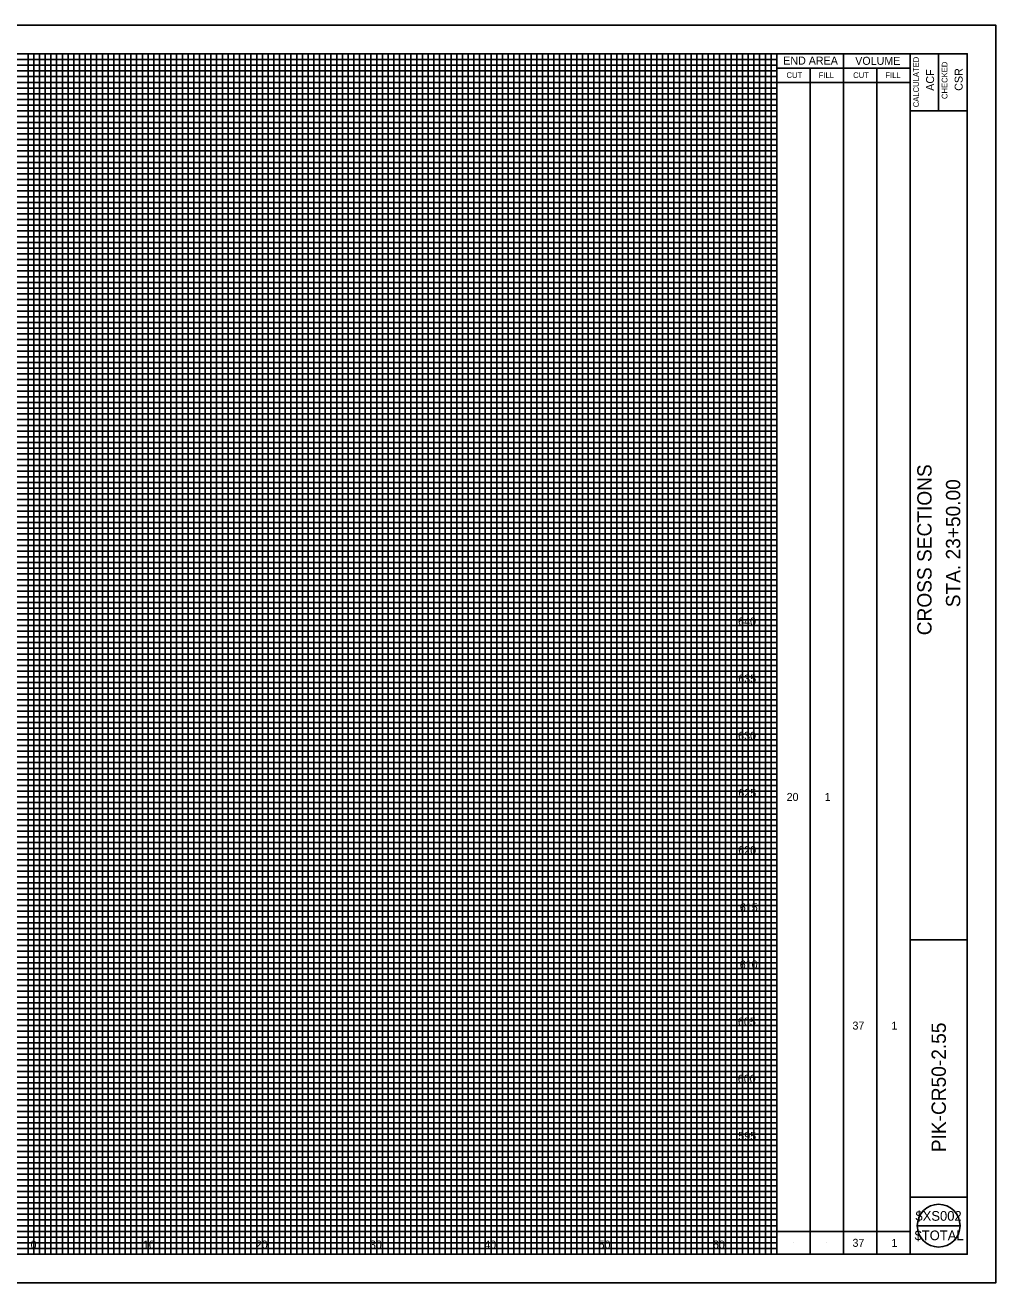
# Model space of a CAD drawing. Extents: x 1858928 to 1859278, y 421672 to 422012.
# Drawn here: x 1859012.6 to 1859097.5, y 421786.6 to 421896.6 of the extents above; entities that cross this region are included whole.
import ezdxf

# ---------------------------------------------------------------- set-up
doc = ezdxf.new("R2010")
doc.units = 0
for name, color, linetype in [('SH_Border', 7, 'Continuous'), ('SH_Cut_Line', 7, 'Continuous'), ('SH_Data', 7, 'Continuous'), ('SH_Major_Grid_Line', 7, 'Continuous'), ('SH_Minor_Grid_Line', 7, 'Continuous'), ('SH_Text', 7, 'Continuous')]:
    doc.layers.add(name, color=color, linetype=linetype)

msp = doc.modelspace()

# ---------------------------------------------------------------- linework, layer by layer
at = {"layer": 'SH_Border'}
for p, q in [((1859090.03, 421789.11), (1859090.03, 421894.11)), ((1859092.53, 421894.11), (1859092.53, 421889.11)), ((1859090.03, 421889.11), (1859095.03, 421889.11)), ((1859090.03, 421816.61), (1859095.03, 421816.61)), ((1859090.03, 421794.11), (1859095.03, 421794.11))]:
    msp.add_line(p, q, dxfattribs=at)
msp.add_lwpolyline([(1858937.53, 421894.11), (1859095.03, 421894.11), (1859095.03, 421789.11), (1858937.53, 421789.11)], close=True, dxfattribs=at)
at = {"layer": 'SH_Cut_Line'}
msp.add_lwpolyline([(1858927.53, 421786.61), (1859097.53, 421786.61), (1859097.53, 421896.61), (1858927.53, 421896.61)], close=True, dxfattribs=at)
at = {"layer": 'SH_Data'}
for p, q in [((1859078.37, 421789.11), (1859078.37, 421894.11)), ((1859084.2, 421789.11), (1859084.2, 421894.11)), ((1859078.37, 421892.86), (1859090.03, 421892.86)), ((1859081.28, 421789.11), (1859081.28, 421892.86)), ((1859087.12, 421789.11), (1859087.12, 421892.86)), ((1859078.37, 421891.61), (1859090.03, 421891.61)), ((1859078.37, 421791.11), (1859090.03, 421791.11)), ((1859090.66, 421791.61), (1859094.41, 421791.61)), ((1859079.83, 421790.11), (1859079.83, 421790.11)), ((1859082.74, 421790.11), (1859082.74, 421790.11)), ((1859085.66, 421790.11), (1859085.66, 421790.11)), ((1859088.58, 421790.11), (1859088.58, 421790.11))]:
    msp.add_line(p, q, dxfattribs=at)
msp.add_circle((1859092.53, 421791.61), 1.87, dxfattribs=at)
at = {"layer": 'SH_Major_Grid_Line'}
for p, q in [((1859013.37, 421789.11), (1859013.37, 421894.11)), ((1859018.37, 421789.11), (1859018.37, 421894.11)), ((1859023.37, 421789.11), (1859023.37, 421894.11)), ((1859028.37, 421789.11), (1859028.37, 421894.11)), ((1859033.37, 421789.11), (1859033.37, 421894.11)), ((1859038.37, 421789.11), (1859038.37, 421894.11)), ((1859043.37, 421789.11), (1859043.37, 421894.11)), ((1859048.37, 421789.11), (1859048.37, 421894.11)), ((1859053.37, 421789.11), (1859053.37, 421894.11)), ((1859058.37, 421789.11), (1859058.37, 421894.11)), ((1859063.37, 421789.11), (1859063.37, 421894.11)), ((1859068.37, 421789.11), (1859068.37, 421894.11)), ((1859073.37, 421789.11), (1859073.37, 421894.11)), ((1858943.37, 421889.11), (1859078.37, 421889.11)), ((1858943.37, 421884.11), (1859078.37, 421884.11)), ((1858943.37, 421879.11), (1859078.37, 421879.11)), ((1858943.37, 421874.11), (1859078.37, 421874.11)), ((1858943.37, 421869.11), (1859078.37, 421869.11)), ((1858943.37, 421864.11), (1859078.37, 421864.11)), ((1858943.37, 421859.11), (1859078.37, 421859.11)), ((1858943.37, 421854.11), (1859078.37, 421854.11)), ((1858943.37, 421849.11), (1859078.37, 421849.11)), ((1858943.37, 421844.11), (1859078.37, 421844.11)), ((1858943.37, 421839.11), (1859078.37, 421839.11)), ((1858943.37, 421834.11), (1859078.37, 421834.11)), ((1858943.37, 421829.11), (1859078.37, 421829.11)), ((1858943.37, 421824.11), (1859078.37, 421824.11)), ((1858943.37, 421819.11), (1859078.37, 421819.11)), ((1858943.37, 421814.11), (1859078.37, 421814.11)), ((1858943.37, 421809.11), (1859078.37, 421809.11)), ((1858943.37, 421804.11), (1859078.37, 421804.11)), ((1858943.37, 421799.11), (1859078.37, 421799.11)), ((1858943.37, 421794.11), (1859078.37, 421794.11))]:
    msp.add_line(p, q, dxfattribs=at)
at = {"layer": 'SH_Minor_Grid_Line'}
for p, q in [((1859012.87, 421789.11), (1859012.87, 421894.11)), ((1859013.87, 421789.11), (1859013.87, 421894.11)), ((1859014.37, 421789.11), (1859014.37, 421894.11)), ((1859014.87, 421789.11), (1859014.87, 421894.11)), ((1859015.37, 421789.11), (1859015.37, 421894.11)), ((1859015.87, 421789.11), (1859015.87, 421894.11)), ((1859016.37, 421789.11), (1859016.37, 421894.11)), ((1859016.87, 421789.11), (1859016.87, 421894.11)), ((1859017.37, 421789.11), (1859017.37, 421894.11)), ((1859017.87, 421789.11), (1859017.87, 421894.11)), ((1859018.87, 421789.11), (1859018.87, 421894.11)), ((1859019.37, 421789.11), (1859019.37, 421894.11)), ((1859019.87, 421789.11), (1859019.87, 421894.11)), ((1859020.37, 421789.11), (1859020.37, 421894.11)), ((1859020.87, 421789.11), (1859020.87, 421894.11)), ((1859021.37, 421789.11), (1859021.37, 421894.11)), ((1859021.87, 421789.11), (1859021.87, 421894.11)), ((1859022.37, 421789.11), (1859022.37, 421894.11)), ((1859022.87, 421789.11), (1859022.87, 421894.11)), ((1859023.87, 421789.11), (1859023.87, 421894.11)), ((1859024.37, 421789.11), (1859024.37, 421894.11)), ((1859024.87, 421789.11), (1859024.87, 421894.11)), ((1859025.37, 421789.11), (1859025.37, 421894.11)), ((1859025.87, 421789.11), (1859025.87, 421894.11)), ((1859026.37, 421789.11), (1859026.37, 421894.11)), ((1859026.87, 421789.11), (1859026.87, 421894.11)), ((1859027.37, 421789.11), (1859027.37, 421894.11)), ((1859027.87, 421789.11), (1859027.87, 421894.11)), ((1859028.87, 421789.11), (1859028.87, 421894.11)), ((1859029.37, 421789.11), (1859029.37, 421894.11)), ((1859029.87, 421789.11), (1859029.87, 421894.11)), ((1859030.37, 421789.11), (1859030.37, 421894.11)), ((1859030.87, 421789.11), (1859030.87, 421894.11)), ((1859031.37, 421789.11), (1859031.37, 421894.11)), ((1859031.87, 421789.11), (1859031.87, 421894.11)), ((1859032.37, 421789.11), (1859032.37, 421894.11)), ((1859032.87, 421789.11), (1859032.87, 421894.11)), ((1859033.87, 421789.11), (1859033.87, 421894.11)), ((1859034.37, 421789.11), (1859034.37, 421894.11)), ((1859034.87, 421789.11), (1859034.87, 421894.11)), ((1859035.37, 421789.11), (1859035.37, 421894.11)), ((1859035.87, 421789.11), (1859035.87, 421894.11)), ((1859036.37, 421789.11), (1859036.37, 421894.11)), ((1859036.87, 421789.11), (1859036.87, 421894.11)), ((1859037.37, 421789.11), (1859037.37, 421894.11)), ((1859037.87, 421789.11), (1859037.87, 421894.11)), ((1859038.87, 421789.11), (1859038.87, 421894.11)), ((1859039.37, 421789.11), (1859039.37, 421894.11)), ((1859039.87, 421789.11), (1859039.87, 421894.11)), ((1859040.37, 421789.11), (1859040.37, 421894.11)), ((1859040.87, 421789.11), (1859040.87, 421894.11)), ((1859041.37, 421789.11), (1859041.37, 421894.11)), ((1859041.87, 421789.11), (1859041.87, 421894.11)), ((1859042.37, 421789.11), (1859042.37, 421894.11)), ((1859042.87, 421789.11), (1859042.87, 421894.11)), ((1859043.87, 421789.11), (1859043.87, 421894.11)), ((1859044.37, 421789.11), (1859044.37, 421894.11)), ((1859044.87, 421789.11), (1859044.87, 421894.11)), ((1859045.37, 421789.11), (1859045.37, 421894.11)), ((1859045.87, 421789.11), (1859045.87, 421894.11)), ((1859046.37, 421789.11), (1859046.37, 421894.11)), ((1859046.87, 421789.11), (1859046.87, 421894.11)), ((1859047.37, 421789.11), (1859047.37, 421894.11)), ((1859047.87, 421789.11), (1859047.87, 421894.11)), ((1859048.87, 421789.11), (1859048.87, 421894.11)), ((1859049.37, 421789.11), (1859049.37, 421894.11)), ((1859049.87, 421789.11), (1859049.87, 421894.11)), ((1859050.37, 421789.11), (1859050.37, 421894.11)), ((1859050.87, 421789.11), (1859050.87, 421894.11)), ((1859051.37, 421789.11), (1859051.37, 421894.11)), ((1859051.87, 421789.11), (1859051.87, 421894.11)), ((1859052.37, 421789.11), (1859052.37, 421894.11)), ((1859052.87, 421789.11), (1859052.87, 421894.11)), ((1859053.87, 421789.11), (1859053.87, 421894.11)), ((1859054.37, 421789.11), (1859054.37, 421894.11)), ((1859054.87, 421789.11), (1859054.87, 421894.11)), ((1859055.37, 421789.11), (1859055.37, 421894.11)), ((1859055.87, 421789.11), (1859055.87, 421894.11)), ((1859056.37, 421789.11), (1859056.37, 421894.11)), ((1859056.87, 421789.11), (1859056.87, 421894.11)), ((1859057.37, 421789.11), (1859057.37, 421894.11)), ((1859057.87, 421789.11), (1859057.87, 421894.11)), ((1859058.87, 421789.11), (1859058.87, 421894.11)), ((1859059.37, 421789.11), (1859059.37, 421894.11)), ((1859059.87, 421789.11), (1859059.87, 421894.11)), ((1859060.37, 421789.11), (1859060.37, 421894.11)), ((1859060.87, 421789.11), (1859060.87, 421894.11)), ((1859061.37, 421789.11), (1859061.37, 421894.11)), ((1859061.87, 421789.11), (1859061.87, 421894.11)), ((1859062.37, 421789.11), (1859062.37, 421894.11)), ((1859062.87, 421789.11), (1859062.87, 421894.11)), ((1859063.87, 421789.11), (1859063.87, 421894.11)), ((1859064.37, 421789.11), (1859064.37, 421894.11)), ((1859064.87, 421789.11), (1859064.87, 421894.11)), ((1859065.37, 421789.11), (1859065.37, 421894.11)), ((1859065.87, 421789.11), (1859065.87, 421894.11)), ((1859066.37, 421789.11), (1859066.37, 421894.11)), ((1859066.87, 421789.11), (1859066.87, 421894.11)), ((1859067.37, 421789.11), (1859067.37, 421894.11)), ((1859067.87, 421789.11), (1859067.87, 421894.11)), ((1859068.87, 421789.11), (1859068.87, 421894.11)), ((1859069.37, 421789.11), (1859069.37, 421894.11)), ((1859069.87, 421789.11), (1859069.87, 421894.11)), ((1859070.37, 421789.11), (1859070.37, 421894.11)), ((1859070.87, 421789.11), (1859070.87, 421894.11)), ((1859071.37, 421789.11), (1859071.37, 421894.11)), ((1859071.87, 421789.11), (1859071.87, 421894.11)), ((1859072.37, 421789.11), (1859072.37, 421894.11)), ((1859072.87, 421789.11), (1859072.87, 421894.11)), ((1859073.87, 421789.11), (1859073.87, 421894.11)), ((1859074.37, 421789.11), (1859074.37, 421894.11)), ((1859074.87, 421789.11), (1859074.87, 421894.11)), ((1859075.37, 421789.11), (1859075.37, 421894.11)), ((1859075.87, 421789.11), (1859075.87, 421894.11)), ((1859076.37, 421789.11), (1859076.37, 421894.11)), ((1859076.87, 421789.11), (1859076.87, 421894.11)), ((1859077.37, 421789.11), (1859077.37, 421894.11)), ((1859077.87, 421789.11), (1859077.87, 421894.11)), ((1858943.37, 421893.61), (1859078.37, 421893.61)), ((1858943.37, 421893.11), (1859078.37, 421893.11)), ((1858943.37, 421892.61), (1859078.37, 421892.61)), ((1858943.37, 421892.11), (1859078.37, 421892.11)), ((1858943.37, 421891.61), (1859078.37, 421891.61)), ((1858943.37, 421891.11), (1859078.37, 421891.11)), ((1858943.37, 421890.61), (1859078.37, 421890.61)), ((1858943.37, 421890.11), (1859078.37, 421890.11)), ((1858943.37, 421889.61), (1859078.37, 421889.61)), ((1858943.37, 421888.61), (1859078.37, 421888.61)), ((1858943.37, 421888.11), (1859078.37, 421888.11)), ((1858943.37, 421887.61), (1859078.37, 421887.61)), ((1858943.37, 421887.11), (1859078.37, 421887.11)), ((1858943.37, 421886.61), (1859078.37, 421886.61)), ((1858943.37, 421886.11), (1859078.37, 421886.11)), ((1858943.37, 421885.61), (1859078.37, 421885.61)), ((1858943.37, 421885.11), (1859078.37, 421885.11)), ((1858943.37, 421884.61), (1859078.37, 421884.61)), ((1858943.37, 421883.61), (1859078.37, 421883.61)), ((1858943.37, 421883.11), (1859078.37, 421883.11)), ((1858943.37, 421882.61), (1859078.37, 421882.61)), ((1858943.37, 421882.11), (1859078.37, 421882.11)), ((1858943.37, 421881.61), (1859078.37, 421881.61)), ((1858943.37, 421881.11), (1859078.37, 421881.11)), ((1858943.37, 421880.61), (1859078.37, 421880.61)), ((1858943.37, 421880.11), (1859078.37, 421880.11)), ((1858943.37, 421879.61), (1859078.37, 421879.61)), ((1858943.37, 421878.61), (1859078.37, 421878.61)), ((1858943.37, 421878.11), (1859078.37, 421878.11)), ((1858943.37, 421877.61), (1859078.37, 421877.61)), ((1858943.37, 421877.11), (1859078.37, 421877.11)), ((1858943.37, 421876.61), (1859078.37, 421876.61)), ((1858943.37, 421876.11), (1859078.37, 421876.11)), ((1858943.37, 421875.61), (1859078.37, 421875.61)), ((1858943.37, 421875.11), (1859078.37, 421875.11)), ((1858943.37, 421874.61), (1859078.37, 421874.61)), ((1858943.37, 421873.61), (1859078.37, 421873.61)), ((1858943.37, 421873.11), (1859078.37, 421873.11)), ((1858943.37, 421872.61), (1859078.37, 421872.61)), ((1858943.37, 421872.11), (1859078.37, 421872.11)), ((1858943.37, 421871.61), (1859078.37, 421871.61)), ((1858943.37, 421871.11), (1859078.37, 421871.11)), ((1858943.37, 421870.61), (1859078.37, 421870.61)), ((1858943.37, 421870.11), (1859078.37, 421870.11)), ((1858943.37, 421869.61), (1859078.37, 421869.61)), ((1858943.37, 421868.61), (1859078.37, 421868.61)), ((1858943.37, 421868.11), (1859078.37, 421868.11)), ((1858943.37, 421867.61), (1859078.37, 421867.61)), ((1858943.37, 421867.11), (1859078.37, 421867.11)), ((1858943.37, 421866.61), (1859078.37, 421866.61)), ((1858943.37, 421866.11), (1859078.37, 421866.11)), ((1858943.37, 421865.61), (1859078.37, 421865.61)), ((1858943.37, 421865.11), (1859078.37, 421865.11)), ((1858943.37, 421864.61), (1859078.37, 421864.61)), ((1858943.37, 421863.61), (1859078.37, 421863.61)), ((1858943.37, 421863.11), (1859078.37, 421863.11)), ((1858943.37, 421862.61), (1859078.37, 421862.61)), ((1858943.37, 421862.11), (1859078.37, 421862.11)), ((1858943.37, 421861.61), (1859078.37, 421861.61)), ((1858943.37, 421861.11), (1859078.37, 421861.11)), ((1858943.37, 421860.61), (1859078.37, 421860.61)), ((1858943.37, 421860.11), (1859078.37, 421860.11)), ((1858943.37, 421859.61), (1859078.37, 421859.61)), ((1858943.37, 421858.61), (1859078.37, 421858.61)), ((1858943.37, 421858.11), (1859078.37, 421858.11)), ((1858943.37, 421857.61), (1859078.37, 421857.61)), ((1858943.37, 421857.11), (1859078.37, 421857.11)), ((1858943.37, 421856.61), (1859078.37, 421856.61)), ((1858943.37, 421856.11), (1859078.37, 421856.11)), ((1858943.37, 421855.61), (1859078.37, 421855.61)), ((1858943.37, 421855.11), (1859078.37, 421855.11)), ((1858943.37, 421854.61), (1859078.37, 421854.61)), ((1858943.37, 421853.61), (1859078.37, 421853.61)), ((1858943.37, 421853.11), (1859078.37, 421853.11)), ((1858943.37, 421852.61), (1859078.37, 421852.61)), ((1858943.37, 421852.11), (1859078.37, 421852.11)), ((1858943.37, 421851.61), (1859078.37, 421851.61)), ((1858943.37, 421851.11), (1859078.37, 421851.11)), ((1858943.37, 421850.61), (1859078.37, 421850.61)), ((1858943.37, 421850.11), (1859078.37, 421850.11)), ((1858943.37, 421849.61), (1859078.37, 421849.61)), ((1858943.37, 421848.61), (1859078.37, 421848.61)), ((1858943.37, 421848.11), (1859078.37, 421848.11)), ((1858943.37, 421847.61), (1859078.37, 421847.61)), ((1858943.37, 421847.11), (1859078.37, 421847.11)), ((1858943.37, 421846.61), (1859078.37, 421846.61)), ((1858943.37, 421846.11), (1859078.37, 421846.11)), ((1858943.37, 421845.61), (1859078.37, 421845.61)), ((1858943.37, 421845.11), (1859078.37, 421845.11)), ((1858943.37, 421844.61), (1859078.37, 421844.61)), ((1858943.37, 421843.61), (1859078.37, 421843.61)), ((1858943.37, 421843.11), (1859078.37, 421843.11)), ((1858943.37, 421842.61), (1859078.37, 421842.61)), ((1858943.37, 421842.11), (1859078.37, 421842.11)), ((1858943.37, 421841.61), (1859078.37, 421841.61)), ((1858943.37, 421841.11), (1859078.37, 421841.11)), ((1858943.37, 421840.61), (1859078.37, 421840.61)), ((1858943.37, 421840.11), (1859078.37, 421840.11)), ((1858943.37, 421839.61), (1859078.37, 421839.61)), ((1858943.37, 421838.61), (1859078.37, 421838.61)), ((1858943.37, 421838.11), (1859078.37, 421838.11)), ((1858943.37, 421837.61), (1859078.37, 421837.61)), ((1858943.37, 421837.11), (1859078.37, 421837.11)), ((1858943.37, 421836.61), (1859078.37, 421836.61)), ((1858943.37, 421836.11), (1859078.37, 421836.11)), ((1858943.37, 421835.61), (1859078.37, 421835.61)), ((1858943.37, 421835.11), (1859078.37, 421835.11)), ((1858943.37, 421834.61), (1859078.37, 421834.61)), ((1858943.37, 421833.61), (1859078.37, 421833.61)), ((1858943.37, 421833.11), (1859078.37, 421833.11)), ((1858943.37, 421832.61), (1859078.37, 421832.61)), ((1858943.37, 421832.11), (1859078.37, 421832.11)), ((1858943.37, 421831.61), (1859078.37, 421831.61)), ((1858943.37, 421831.11), (1859078.37, 421831.11)), ((1858943.37, 421830.61), (1859078.37, 421830.61)), ((1858943.37, 421830.11), (1859078.37, 421830.11)), ((1858943.37, 421829.61), (1859078.37, 421829.61)), ((1858943.37, 421828.61), (1859078.37, 421828.61)), ((1858943.37, 421828.11), (1859078.37, 421828.11)), ((1858943.37, 421827.61), (1859078.37, 421827.61)), ((1858943.37, 421827.11), (1859078.37, 421827.11)), ((1858943.37, 421826.61), (1859078.37, 421826.61)), ((1858943.37, 421826.11), (1859078.37, 421826.11)), ((1858943.37, 421825.61), (1859078.37, 421825.61)), ((1858943.37, 421825.11), (1859078.37, 421825.11)), ((1858943.37, 421824.61), (1859078.37, 421824.61)), ((1858943.37, 421823.61), (1859078.37, 421823.61)), ((1858943.37, 421823.11), (1859078.37, 421823.11)), ((1858943.37, 421822.61), (1859078.37, 421822.61)), ((1858943.37, 421822.11), (1859078.37, 421822.11)), ((1858943.37, 421821.61), (1859078.37, 421821.61)), ((1858943.37, 421821.11), (1859078.37, 421821.11)), ((1858943.37, 421820.61), (1859078.37, 421820.61)), ((1858943.37, 421820.11), (1859078.37, 421820.11)), ((1858943.37, 421819.61), (1859078.37, 421819.61)), ((1858943.37, 421818.61), (1859078.37, 421818.61)), ((1858943.37, 421818.11), (1859078.37, 421818.11)), ((1858943.37, 421817.61), (1859078.37, 421817.61)), ((1858943.37, 421817.11), (1859078.37, 421817.11)), ((1858943.37, 421816.61), (1859078.37, 421816.61)), ((1858943.37, 421816.11), (1859078.37, 421816.11)), ((1858943.37, 421815.61), (1859078.37, 421815.61)), ((1858943.37, 421815.11), (1859078.37, 421815.11)), ((1858943.37, 421814.61), (1859078.37, 421814.61)), ((1858943.37, 421813.61), (1859078.37, 421813.61)), ((1858943.37, 421813.11), (1859078.37, 421813.11)), ((1858943.37, 421812.61), (1859078.37, 421812.61)), ((1858943.37, 421812.11), (1859078.37, 421812.11)), ((1858943.37, 421811.61), (1859078.37, 421811.61)), ((1858943.37, 421811.11), (1859078.37, 421811.11)), ((1858943.37, 421810.61), (1859078.37, 421810.61)), ((1858943.37, 421810.11), (1859078.37, 421810.11)), ((1858943.37, 421809.61), (1859078.37, 421809.61)), ((1858943.37, 421808.61), (1859078.37, 421808.61)), ((1858943.37, 421808.11), (1859078.37, 421808.11)), ((1858943.37, 421807.61), (1859078.37, 421807.61)), ((1858943.37, 421807.11), (1859078.37, 421807.11)), ((1858943.37, 421806.61), (1859078.37, 421806.61)), ((1858943.37, 421806.11), (1859078.37, 421806.11)), ((1858943.37, 421805.61), (1859078.37, 421805.61)), ((1858943.37, 421805.11), (1859078.37, 421805.11)), ((1858943.37, 421804.61), (1859078.37, 421804.61)), ((1858943.37, 421803.61), (1859078.37, 421803.61)), ((1858943.37, 421803.11), (1859078.37, 421803.11)), ((1858943.37, 421802.61), (1859078.37, 421802.61)), ((1858943.37, 421802.11), (1859078.37, 421802.11)), ((1858943.37, 421801.61), (1859078.37, 421801.61)), ((1858943.37, 421801.11), (1859078.37, 421801.11)), ((1858943.37, 421800.61), (1859078.37, 421800.61)), ((1858943.37, 421800.11), (1859078.37, 421800.11)), ((1858943.37, 421799.61), (1859078.37, 421799.61)), ((1858943.37, 421798.61), (1859078.37, 421798.61)), ((1858943.37, 421798.11), (1859078.37, 421798.11)), ((1858943.37, 421797.61), (1859078.37, 421797.61)), ((1858943.37, 421797.11), (1859078.37, 421797.11)), ((1858943.37, 421796.61), (1859078.37, 421796.61)), ((1858943.37, 421796.11), (1859078.37, 421796.11)), ((1858943.37, 421795.61), (1859078.37, 421795.61)), ((1858943.37, 421795.11), (1859078.37, 421795.11)), ((1858943.37, 421794.61), (1859078.37, 421794.61)), ((1858943.37, 421793.61), (1859078.37, 421793.61)), ((1858943.37, 421793.11), (1859078.37, 421793.11)), ((1858943.37, 421792.61), (1859078.37, 421792.61)), ((1858943.37, 421792.11), (1859078.37, 421792.11)), ((1858943.37, 421791.61), (1859078.37, 421791.61)), ((1858943.37, 421791.11), (1859078.37, 421791.11)), ((1858943.37, 421790.61), (1859078.37, 421790.61)), ((1858943.37, 421790.11), (1859078.37, 421790.11)), ((1858943.37, 421789.61), (1859078.37, 421789.61))]:
    msp.add_line(p, q, dxfattribs=at)

# ---------------------------------------------------------------- texts
at = {"layer": 'SH_Data'}
for s, height, p in [('END AREA', 0.7, (1859078.93, 421893.16)), ('VOLUME', 0.7, (1859085.23, 421893.14)), ('CUT', 0.5, (1859079.22, 421891.99)), ('FILL', 0.5, (1859082.04, 421891.99)), ('CUT', 0.5, (1859085.05, 421891.99)), ('FILL', 0.5, (1859087.87, 421891.99)), ('$XS002', 0.85, (1859090.5, 421792.04)), ('$TOTAL', 0.85, (1859090.42, 421790.34))]:
    msp.add_text(s, height=height, dxfattribs=at).set_placement(p)
for s, height, p in [('CALCULATED', 0.5, (1859090.8, 421889.43)), ('CHECKED', 0.5, (1859093.3, 421890.15)), ('ACF', 0.7, (1859092.13, 421890.87)), ('CSR', 0.7, (1859094.63, 421890.87)), ('CROSS SECTIONS', 1.25, (1859091.91, 421843.25)), ('STA. 23+50.00', 1.25, (1859094.42, 421845.7)), ('PIK-CR50-2.55', 1.25, (1859093.16, 421798.04))]:
    msp.add_text(s, height=height, rotation=90, dxfattribs=at).set_placement(p)
at = {"layer": 'SH_Text'}
for s, p in [('640', (1859074.99, 421844.11)), ('635', (1859075, 421839.11)), ('630', (1859074.99, 421834.11)), ('625', (1859075.01, 421829.11)), ('20', (1859079.23, 421828.76)), ('1', (1859082.56, 421828.76)), ('620', (1859075, 421824.11)), ('615', (1859075.14, 421819.11)), ('610', (1859075.13, 421814.11)), ('605', (1859074.97, 421809.11)), ('37', (1859084.99, 421808.76)), ('1', (1859088.4, 421808.76)), ('600', (1859074.96, 421804.11)), ('595', (1859075, 421799.11)), ('0', (1859013.09, 421789.61)), ('0', (1859013.09, 421789.61)), ('10', (1859022.92, 421789.61)), ('20', (1859032.79, 421789.61)), ('30', (1859042.78, 421789.61)), ('40', (1859052.78, 421789.61)), ('50', (1859062.78, 421789.61)), ('60', (1859072.78, 421789.61)), ('37', (1859084.99, 421789.76)), ('1', (1859088.4, 421789.76))]:
    msp.add_text(s, height=0.7, dxfattribs=at).set_placement(p)

doc.saveas('drawing.dxf')
